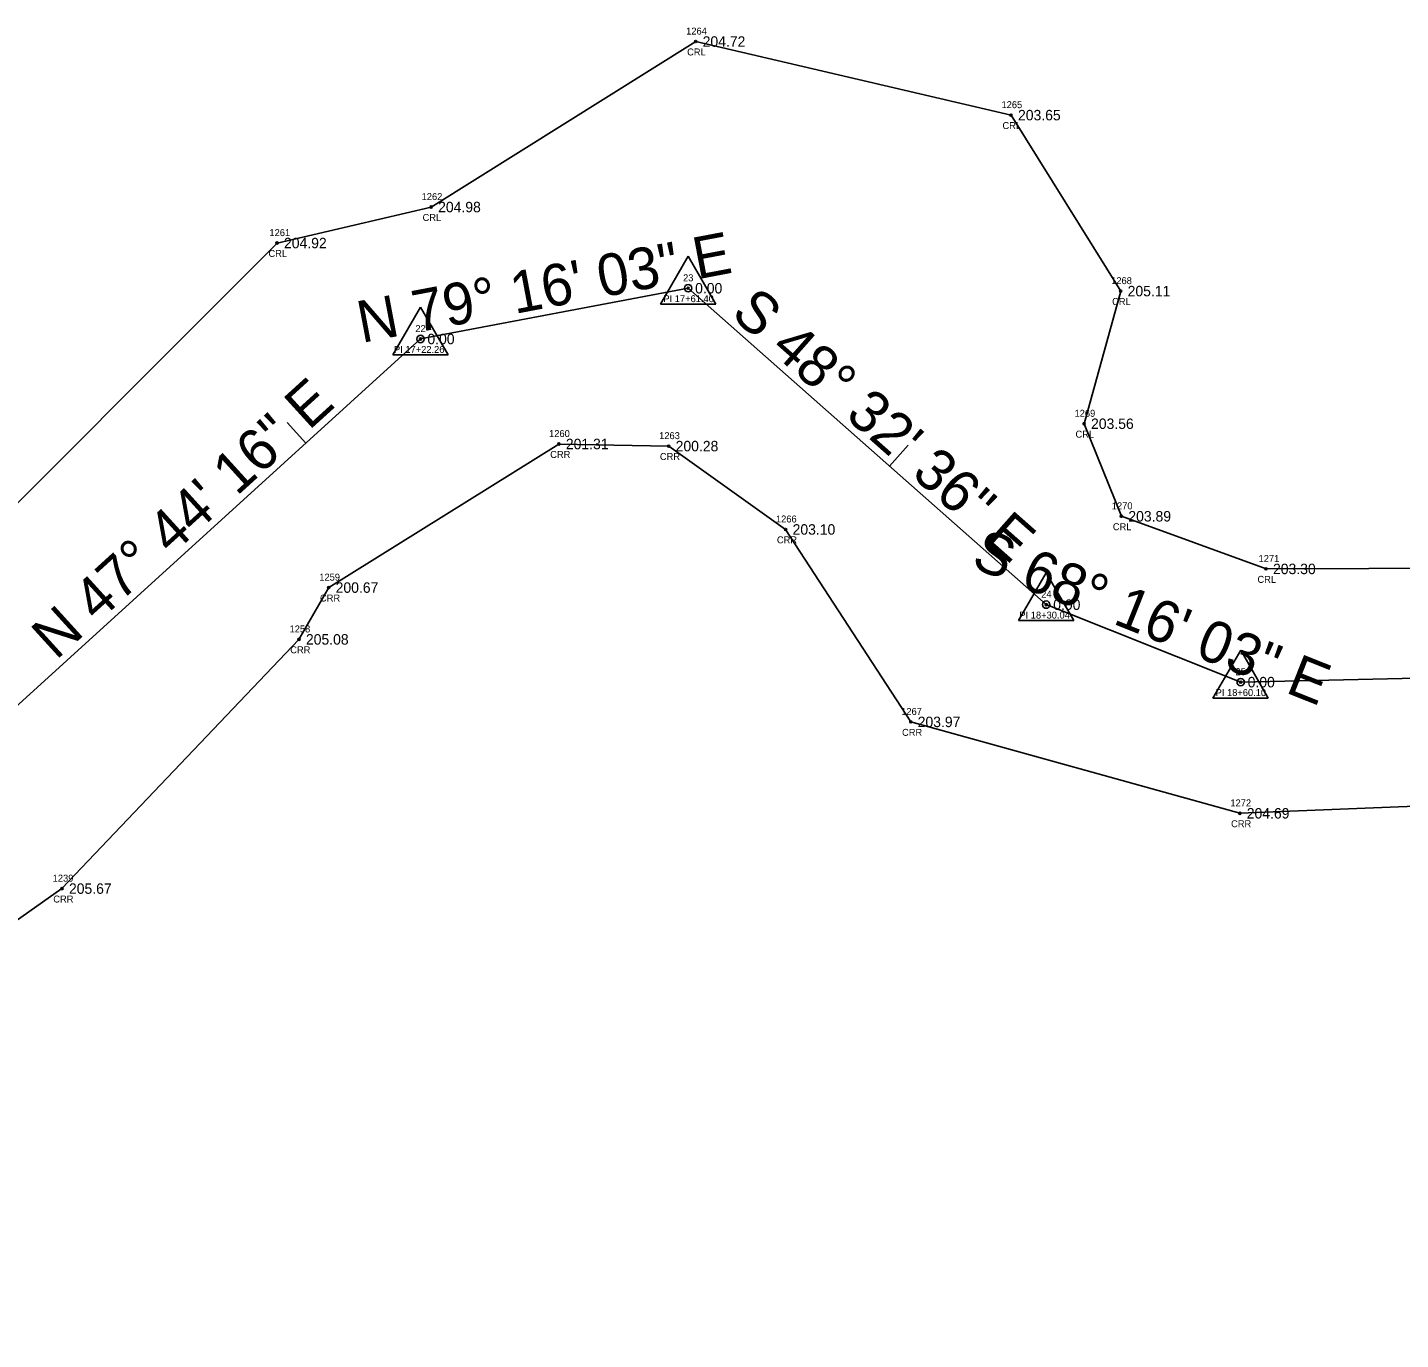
# Model space of a CAD drawing. Extents: x 2259948 to 2261336, y 1064647 to 1065986.
# Drawn here: x 2260900.1 to 2261097.4, y 1065077.8 to 1065266.2 of the extents above; entities that cross this region are included whole.
import ezdxf

# ---------------------------------------------------------------- set-up
doc = ezdxf.new("R2010")
doc.units = 0
for name, color, linetype in [('RD_EX_H2O', 7, 'Continuous'), ('RD_EX_H2O_txCode', 7, 'Continuous'), ('RD_EX_TX_H2O_ELEV', 7, 'Continuous'), ('RD_HC_Cl', 7, 'Continuous'), ('RD_HC_Data', 7, 'Continuous'), ('RD_HC_Data_Tic', 7, 'Continuous'), ('RD_HC_Survey_ELEV', 7, 'Continuous'), ('RD_HC_txCode', 7, 'Continuous'), ('RD_SMD_Locator', 7, 'Continuous')]:
    doc.layers.add(name, color=color, linetype=linetype)

msp = doc.modelspace()

# ---------------------------------------------------------------- linework, layer by layer
at = {"layer": 'RD_EX_H2O'}
for points in [[(2260885.41, 1065184.64), (2260936, 1065235.25), (2260958.14, 1065240.42), (2260996.14, 1065264.19), (2261041.44, 1065253.62), (2261057.19, 1065228.35), (2261051.93, 1065209.3), (2261057.29, 1065196.01), (2261078.07, 1065188.45), (2261181.25, 1065188.78), (2261285.07, 1065214.16)], [(2260835.04, 1065077.78), (2260839.45, 1065081.34), (2260836.25, 1065093.94), (2260905.11, 1065142.54), (2260939.15, 1065178.33), (2260943.42, 1065185.77), (2260976.49, 1065206.39), (2260992.26, 1065206.09), (2261009.06, 1065194.12), (2261027.03, 1065166.48), (2261074.3, 1065153.35), (2261181.18, 1065157.65), (2261291.85, 1065184.94)]]:
    msp.add_lwpolyline(points, dxfattribs=at)
at = {"layer": 'RD_HC_Cl'}
for p, q in [((2260956.6, 1065221.47), (2260995.06, 1065228.76)), ((2260995.06, 1065228.76), (2261046.5, 1065183.32)), ((2260894.66, 1065165.19), (2260956.6, 1065221.47)), ((2261046.5, 1065183.32), (2261074.43, 1065172.19)), ((2261074.43, 1065172.19), (2261183.27, 1065174.61))]:
    msp.add_line(p, q, dxfattribs=at)
at = {"layer": 'RD_HC_Data'}
for p, q in [((2260991.09, 1065226.47), (2260995.06, 1065233.35)), ((2260995.06, 1065233.35), (2260999.03, 1065226.47)), ((2260952.63, 1065219.18), (2260956.6, 1065226.06)), ((2260956.6, 1065226.06), (2260960.57, 1065219.18)), ((2260991.09, 1065226.47), (2260999.03, 1065226.47)), ((2260952.63, 1065219.18), (2260960.57, 1065219.18)), ((2261042.53, 1065181.02), (2261046.5, 1065187.9)), ((2261046.5, 1065187.9), (2261050.47, 1065181.02)), ((2261042.53, 1065181.02), (2261050.47, 1065181.02)), ((2261070.45, 1065169.89), (2261074.43, 1065176.77)), ((2261074.43, 1065176.77), (2261078.4, 1065169.89)), ((2261070.45, 1065169.89), (2261078.4, 1065169.89))]:
    msp.add_line(p, q, dxfattribs=at)
for centre in [(2260995.06, 1065228.76), (2260956.6, 1065221.47), (2261046.5, 1065183.32), (2261074.43, 1065172.19)]:
    msp.add_circle(centre, 0.529, dxfattribs=at)
at = {"layer": 'RD_HC_Data_Tic'}
for p, q in [((2260940.13, 1065206.5), (2260937.44, 1065209.46)), ((2261023.99, 1065203.21), (2261026.64, 1065206.2))]:
    msp.add_line(p, q, dxfattribs=at)
at = {"layer": 'RD_SMD_Locator'}
for centre in [(2260996.14, 1065264.19), (2261041.44, 1065253.62), (2260958.14, 1065240.42), (2260936, 1065235.25), (2260995.06, 1065228.76), (2261057.19, 1065228.35), (2260956.6, 1065221.47), (2261051.93, 1065209.3), (2260976.49, 1065206.39), (2260992.26, 1065206.09), (2261057.29, 1065196.01), (2261009.06, 1065194.12), (2261078.07, 1065188.45), (2260943.42, 1065185.77), (2261046.5, 1065183.32), (2260939.15, 1065178.33), (2261074.43, 1065172.19), (2261027.03, 1065166.48), (2261074.3, 1065153.35), (2260905.11, 1065142.54)]:
    msp.add_circle(centre, 0.15, dxfattribs=at)

# ---------------------------------------------------------------- texts
at = {"layer": 'RD_EX_H2O_txCode'}
for s, p in [('1264', (2260994.77, 1065265.19)), ('CRL', (2260994.91, 1065262.19)), ('1265', (2261040.07, 1065254.62)), ('CRL', (2261040.21, 1065251.62)), ('1262', (2260956.77, 1065241.42)), ('CRL', (2260956.91, 1065238.42)), ('1261', (2260934.91, 1065236.25)), ('CRL', (2260934.77, 1065233.25)), ('1268', (2261055.82, 1065229.35)), ('CRL', (2261055.96, 1065226.35)), ('1269', (2261050.56, 1065210.3)), ('1260', (2260975.08, 1065207.39)), ('CRL', (2261050.7, 1065207.3)), ('1263', (2260990.89, 1065207.09)), ('CRR', (2260975.24, 1065204.39)), ('CRR', (2260991, 1065204.09)), ('1270', (2261055.91, 1065197.01)), ('1266', (2261007.67, 1065195.12)), ('CRL', (2261056.06, 1065194.01)), ('CRR', (2261007.81, 1065192.12)), ('1271', (2261077, 1065189.45)), ('1259', (2260942.07, 1065186.77)), ('CRL', (2261076.84, 1065186.45)), ('CRR', (2260942.17, 1065183.77)), ('1258', (2260937.8, 1065179.33)), ('CRR', (2260937.9, 1065176.33)), ('1267', (2261025.66, 1065167.48)), ('CRR', (2261025.78, 1065164.48)), ('1272', (2261072.95, 1065154.35)), ('CRR', (2261073.05, 1065151.35)), ('1239', (2260903.77, 1065143.54)), ('CRR', (2260903.86, 1065140.54))]:
    msp.add_text(s, height=1, dxfattribs=at).set_placement(p)
at = {"layer": 'RD_EX_TX_H2O_ELEV'}
for s, p in [('204.72', (2260997.14, 1065263.44)), ('203.65', (2261042.44, 1065252.87)), ('204.98', (2260959.14, 1065239.67)), ('204.92', (2260937, 1065234.5)), ('205.11', (2261058.19, 1065227.6)), ('203.56', (2261052.93, 1065208.55)), ('201.31', (2260977.49, 1065205.64)), ('200.28', (2260993.26, 1065205.34)), ('203.89', (2261058.29, 1065195.26)), ('203.10', (2261010.06, 1065193.37)), ('203.30', (2261079.07, 1065187.7)), ('200.67', (2260944.42, 1065185.02)), ('205.08', (2260940.15, 1065177.58)), ('203.97', (2261028.03, 1065165.73)), ('204.69', (2261075.3, 1065152.6)), ('205.67', (2260906.11, 1065141.79))]:
    msp.add_text(s, height=1.5, dxfattribs=at).set_placement(p)
at = {"layer": 'RD_HC_Data'}
for s, rotation, p in [('N 79%%d 16\' 03" E', 10.7326, (2260948.15, 1065220.89)), ('S 48%%d 32\' 36" E', 318.5433, (2261001.02, 1065224.82)), ('N 47%%d 44\' 16" E', 42.2621, (2260904.25, 1065175.25)), ('S 68%%d 16\' 03" E', 338.2676, (2261035.53, 1065188.77))]:
    msp.add_text(s, height=6, rotation=rotation, dxfattribs=at).set_placement(p)
at = {"layer": 'RD_HC_Survey_ELEV'}
for p in [(2260996.06, 1065228.01), (2260957.6, 1065220.72), (2261047.5, 1065182.57), (2261075.43, 1065171.44)]:
    msp.add_text('0.00', height=1.5, dxfattribs=at).set_placement(p)
at = {"layer": 'RD_HC_txCode'}
for s, p in [('23', (2260994.33, 1065229.76)), ('PI 17+61.40', (2260991.5, 1065226.76)), ('22', (2260955.87, 1065222.47)), ('PI 17+22.26', (2260952.8, 1065219.47)), ('24', (2261045.77, 1065184.32)), ('PI 18+30.04', (2261042.64, 1065181.32)), ('25', (2261073.69, 1065173.19)), ('PI 18+60.10', (2261070.83, 1065170.19))]:
    msp.add_text(s, height=1, dxfattribs=at).set_placement(p)

doc.saveas('drawing.dxf')
